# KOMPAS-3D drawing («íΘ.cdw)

Referenced files: общ.cdw
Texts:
  Реконструкция элеткроснабжения помещений 2 го этажа  первой детской городской больницы
  Microsoft
  Текст на чертеже
  Размерные надписи
  Шероховатость
  Линия-выноска #1
  Линия-выноска #2
  Линия-выноска #3
  Отклонения формы и база
  Заголовок таблицы
  Ячейка таблицы
  Стрелка вида
  Обозначение изменения
  Фигурная скобка
  Номер узла
  Марка координационной оси
  VRCB
  Выносная надпись
  Обозначение узла
  Марка/позиционное обозначение с линией-выноской
  Марка/позиционное обозначение на линии
  Марка/позиционное обозначение без линии-выноски
  Номер группы
  Р кВт
  Ток, А
  Гр1
  Гр2
  Гр3
  Гр4
  ВА 88-32 (3)
  ВА 47-29 (3)
  Щиток РЩ1
  к заземлителю
  ПВ 1х10 мм 2
  ВРУ (ЩМП-3)
  Рр=55.0 кВт
  Гр5
  Гр6
  Гр7
  Гр8
  Щиток РЩ2
  Щиток РЩ3
  Щиток РЩ4
  Щиток РЩ5
  Щиток РЩ6
  Щиток РЩ7
  Щиток ЩК
  ВА 47-29 (1)
  Гр9
  Щиток ЩАО
  CONTINUOUS0
  Реконструкция элеткроснабжения помещений 2 го этажа
  первой детской городской больницы
  ГИП
  Волков
  Разработ
  Смирнов
  Однолинейная схема ВРУ
  ООО "ЭнАуд"
Dimensions and other numbers on the sheet: 41/12-2009.ЭС; 7; 13.22; 20.2; 5.0; 7.9; 100А; 20А; 16А; 40А; 15.00; 24.4; 10А; 0.48; 2.4; 4; 1:1; 5; 0; 1; 2; 3; 6; 8; 9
